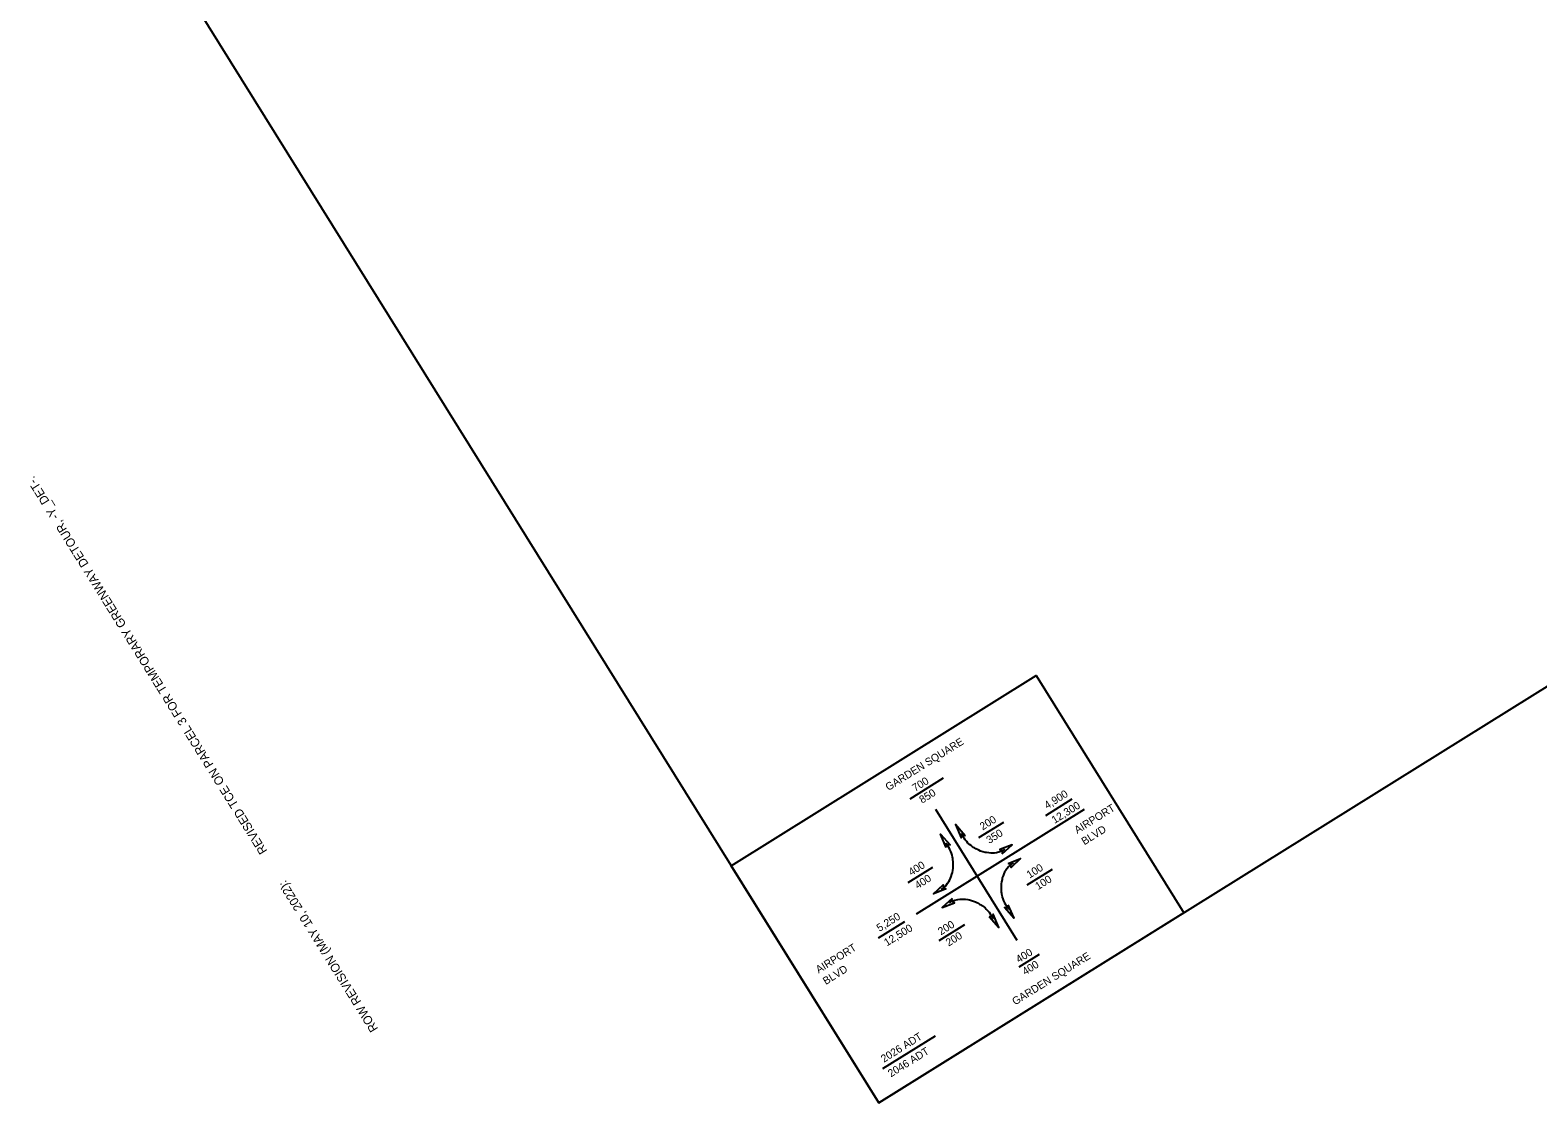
# Model space of a CAD drawing. Extents: x 2045918 to 2047994, y 757573 to 759227.
# Drawn here: x 2045918 to 2046954, y 757573 to 758310 of the extents above; entities that cross this region are included whole.
import ezdxf

# ---------------------------------------------------------------- set-up
doc = ezdxf.new("R2010")
doc.units = 0
for name, color, linetype in [('Prop Grid Mask', 7, 'Continuous'), ('Sheet Block Revision CELL', 7, 'Continuous'), ('Sheet Clip Boundary CELL', 7, 'Continuous')]:
    doc.layers.add(name, color=color, linetype=linetype)

msp = doc.modelspace()

# ---------------------------------------------------------------- linework, layer by layer
at = {"layer": 'Prop Grid Mask'}
for p, q in [((2046522.9, 757782.1), (2046545.9, 757796.4)), ((2046642.6, 757774.8), (2046527.2, 757702.9)), ((2046596.5, 757684.8), (2046540.5, 757774.8)), ((2046596.5, 757684.8), (2046540.5, 757774.8)), ((2046616.3, 757770.7), (2046634.4, 757782)), ((2046570.2, 757755.4), (2046587.3, 757766.1)), ((2046547.7, 757751.5), (2046547.5, 757751.7)), ((2046548, 757751.1), (2046547.7, 757751.5)), ((2046548.4, 757750.5), (2046548, 757751.1)), ((2046558.3, 757758.1), (2046558.2, 757758.3)), ((2046558.5, 757757.6), (2046558.3, 757758.1)), ((2046558.8, 757757), (2046558.5, 757757.6)), ((2046559.1, 757756.4), (2046558.8, 757757)), ((2046559.5, 757755.7), (2046559.1, 757756.4)), ((2046560, 757755), (2046559.5, 757755.7)), ((2046560.8, 757753.9), (2046560, 757755)), ((2046561.9, 757752.7), (2046560.8, 757753.9)), ((2046562.7, 757751.7), (2046561.9, 757752.7)), ((2046563.7, 757750.8), (2046562.7, 757751.7)), ((2046548.8, 757750), (2046548.4, 757750.5)), ((2046549.2, 757749.3), (2046548.8, 757750)), ((2046549.7, 757748.5), (2046549.2, 757749.3)), ((2046550.3, 757747.3), (2046549.7, 757748.5)), ((2046551, 757745.9), (2046550.3, 757747.3)), ((2046551.4, 757744.7), (2046551, 757745.9)), ((2046551.8, 757743.4), (2046551.4, 757744.7)), ((2046552.1, 757742), (2046551.8, 757743.4)), ((2046552.2, 757741.3), (2046552.1, 757742)), ((2046552.3, 757740.7), (2046552.2, 757741.3)), ((2046564.8, 757749.9), (2046563.7, 757750.8)), ((2046565.4, 757749.5), (2046564.8, 757749.9)), ((2046565.9, 757749.1), (2046565.4, 757749.5)), ((2046566.5, 757748.7), (2046565.9, 757749.1)), ((2046567.3, 757748.2), (2046566.5, 757748.7)), ((2046568.2, 757747.7), (2046567.3, 757748.2)), ((2046569.2, 757747.2), (2046568.2, 757747.7)), ((2046570.2, 757746.7), (2046569.2, 757747.2)), ((2046571.4, 757746.2), (2046570.2, 757746.7)), ((2046573, 757745.7), (2046571.4, 757746.2)), ((2046574.4, 757745.3), (2046573, 757745.7)), ((2046575.5, 757745.1), (2046574.4, 757745.3)), ((2046577, 757744.9), (2046575.5, 757745.1)), ((2046578.5, 757744.8), (2046577, 757744.9)), ((2046579.7, 757744.8), (2046578.5, 757744.8)), ((2046580.9, 757744.8), (2046579.7, 757744.8)), ((2046582.4, 757745), (2046580.9, 757744.8)), ((2046584.5, 757745.6), (2046582.4, 757745)), ((2046586.4, 757746.3), (2046584.5, 757745.6)), ((2046588, 757747.2), (2046586.4, 757746.3)), ((2046521.7, 757724.7), (2046538.5, 757735.2)), ((2046551.7, 757730.3), (2046552, 757731.4)), ((2046552, 757731.4), (2046552.3, 757732.8)), ((2046552.4, 757740), (2046552.3, 757740.7)), ((2046552.3, 757732.8), (2046552.5, 757734.4)), ((2046552.6, 757739), (2046552.4, 757740)), ((2046552.5, 757734.4), (2046552.6, 757735.8)), ((2046552.6, 757738), (2046552.6, 757739)), ((2046552.6, 757736.9), (2046552.6, 757738)), ((2046552.6, 757735.8), (2046552.6, 757736.9)), ((2046587.4, 757730.5), (2046586.8, 757729.2)), ((2046587.9, 757731.6), (2046587.4, 757730.5)), ((2046588.5, 757732.6), (2046587.9, 757731.6)), ((2046589.3, 757733.9), (2046588.5, 757732.6)), ((2046590.7, 757735.6), (2046589.3, 757733.9)), ((2046592.2, 757736.9), (2046590.7, 757735.6)), ((2046593.8, 757738), (2046592.2, 757736.9)), ((2046603.3, 757722.9), (2046620.7, 757733.7)), ((2046544.3, 757720), (2046545.8, 757721)), ((2046545.8, 757721), (2046547.4, 757722.4)), ((2046547.4, 757722.4), (2046548.7, 757724.1)), ((2046548.7, 757724.1), (2046549.6, 757725.3)), ((2046549.6, 757725.3), (2046550.2, 757726.4)), ((2046550.2, 757726.4), (2046550.7, 757727.5)), ((2046550.7, 757727.5), (2046551.2, 757728.8)), ((2046551.2, 757728.8), (2046551.7, 757730.3)), ((2046585.5, 757722.2), (2046585.4, 757721.1)), ((2046585.4, 757721.1), (2046585.5, 757719.9)), ((2046585.6, 757723.6), (2046585.5, 757722.2)), ((2046585.8, 757725.1), (2046585.6, 757723.6)), ((2046586.1, 757726.6), (2046585.8, 757725.1)), ((2046586.3, 757727.7), (2046586.1, 757726.6)), ((2046586.8, 757729.2), (2046586.3, 757727.7)), ((2046550, 757710.7), (2046551.7, 757711.7)), ((2046551.7, 757711.7), (2046553.6, 757712.4)), ((2046553.6, 757712.4), (2046555.7, 757712.9)), ((2046555.7, 757712.9), (2046557.2, 757713.1)), ((2046557.2, 757713.1), (2046558.4, 757713.2)), ((2046558.4, 757713.2), (2046559.6, 757713.2)), ((2046559.6, 757713.2), (2046561, 757713.1)), ((2046561, 757713.1), (2046562.6, 757712.9)), ((2046562.6, 757712.9), (2046563.7, 757712.7)), ((2046563.7, 757712.7), (2046565.1, 757712.3)), ((2046565.1, 757712.3), (2046566.6, 757711.8)), ((2046566.6, 757711.8), (2046567.9, 757711.3)), ((2046567.9, 757711.3), (2046568.9, 757710.8)), ((2046568.9, 757710.8), (2046569.9, 757710.3)), ((2046569.9, 757710.3), (2046570.7, 757709.8)), ((2046570.7, 757709.8), (2046571.6, 757709.3)), ((2046585.5, 757719.9), (2046585.5, 757719)), ((2046585.5, 757719), (2046585.6, 757718)), ((2046585.6, 757718), (2046585.7, 757717.3)), ((2046585.7, 757717.3), (2046585.8, 757716.7)), ((2046585.8, 757716.7), (2046586, 757715.9)), ((2046586, 757715.9), (2046586.3, 757714.6)), ((2046586.3, 757714.6), (2046586.7, 757713.3)), ((2046586.7, 757713.3), (2046587.1, 757712.1)), ((2046587.1, 757712.1), (2046587.7, 757710.7)), ((2046587.7, 757710.7), (2046588.4, 757709.5)), ((2046571.6, 757709.3), (2046572.2, 757708.8)), ((2046572.2, 757708.8), (2046572.7, 757708.5)), ((2046572.7, 757708.5), (2046573.3, 757708)), ((2046573.3, 757708), (2046574.4, 757707.1)), ((2046574.4, 757707.1), (2046575.3, 757706.2)), ((2046575.3, 757706.2), (2046576.2, 757705.3)), ((2046576.2, 757705.3), (2046577.2, 757704.1)), ((2046577.2, 757704.1), (2046578, 757703)), ((2046578, 757703), (2046578.5, 757702.2)), ((2046578.5, 757702.2), (2046578.9, 757701.6)), ((2046578.9, 757701.6), (2046579.3, 757701)), ((2046579.3, 757701), (2046579.6, 757700.3)), ((2046579.6, 757700.3), (2046579.8, 757699.9)), ((2046579.8, 757699.9), (2046579.9, 757699.6)), ((2046588.4, 757709.5), (2046588.8, 757708.7)), ((2046588.8, 757708.7), (2046589.3, 757708)), ((2046589.3, 757708), (2046589.6, 757707.5)), ((2046589.6, 757707.5), (2046590.1, 757706.9)), ((2046590.1, 757706.9), (2046590.4, 757706.5)), ((2046590.4, 757706.5), (2046590.6, 757706.3)), ((2046501.2, 757686.5), (2046519.2, 757697.8)), ((2046542.9, 757684.7), (2046560.6, 757695.7)), ((2046597.9, 757666.7), (2046611.8, 757675.3)), ((2046504.1, 757596.7), (2046540.4, 757619.3))]:
    msp.add_line(p, q, dxfattribs=at)
for points in [[(2046400, 757736.1), (2046609.6, 757866.7), (2046711, 757703.8), (2046501.4, 757573.3)], [(2046560.7, 757756.7), (2046554.2, 757764.4), (2046558, 757755.2), (2046558.8, 757757)], [(2046547.8, 757748.6), (2046543.8, 757757.9), (2046550.4, 757750.4), (2046548.4, 757750.5)], [(2046586.3, 757744.3), (2046593.1, 757750.5), (2046584.6, 757747.3), (2046586.4, 757746.3)], [(2046590.4, 757737.7), (2046598.9, 757741.1), (2046592.4, 757734.9), (2046592.2, 757736.9)], [(2046547.7, 757720.3), (2046539.1, 757716.9), (2046545.7, 757723.1), (2046545.8, 757721)], [(2046551.8, 757713.7), (2046545, 757707.5), (2046553.5, 757710.6), (2046551.7, 757711.7)], [(2046577.3, 757701.3), (2046583.9, 757693.6), (2046580.1, 757702.8), (2046579.3, 757701)], [(2046590.2, 757709.3), (2046594.3, 757700.1), (2046587.7, 757707.5), (2046589.7, 757707.5)]]:
    msp.add_lwpolyline(points, close=True, dxfattribs=at)
at = {"layer": 'Sheet Clip Boundary CELL'}
msp.add_lwpolyline([(2045946.3, 758464.5), (2046501.4, 757573.2), (2047629.6, 758276), (2047267.8, 758924.3), (2047213.8, 759021), (2047202.5, 759006.9), (2047161.3, 758941.5), (2047057.3, 758924.6), (2047003.6, 759005.9), (2046934.2, 758962.7), (2046881.6, 759047.1)], close=True, dxfattribs=at)

# ---------------------------------------------------------------- texts
at = {"layer": 'Prop Grid Mask'}
for s, rotation, p in [('GARDEN SQUARE', 31.918, (2046508, 757787.4)), ('700', 31.918, (2046526.4, 757786.8)), ('850', 31.918, (2046531.2, 757778.7)), ('4,900', 31.918, (2046617.1, 757774.8)), ('12,300', 31.918, (2046622.2, 757764.8)), ('AIRPORT', 31.918, (2046637.8, 757757.9)), ('200', 31.9187, (2046572.8, 757760.3)), ('BLVD', 31.918, (2046642.7, 757750.1)), ('350', 31.9187, (2046577.3, 757751)), ('400', 31.9187, (2046523.8, 757729)), ('100', 31.9187, (2046605, 757727.2)), ('400', 31.9187, (2046528.1, 757719.9)), ('100', 31.9187, (2046610.9, 757719.3)), ('5,250', 31.918, (2046501.9, 757690.6)), ('12,500', 31.918, (2046507, 757680.6)), ('200', 31.9187, (2046544.1, 757688.2)), ('200', 31.9187, (2046549.4, 757680.5)), ('AIRPORT', 31.918, (2046460.1, 757662)), ('400', 31.918, (2046597.7, 757669.1)), ('GARDEN SQUARE', 31.918, (2046595.1, 757640.1)), ('400', 31.918, (2046602, 757660.7)), ('BLVD', 31.918, (2046465, 757654.1)), ('2026 ADT', 31.918, (2046504.9, 757600.7)), ('2046 ADT', 31.918, (2046509.7, 757590.6))]:
    msp.add_text(s, height=5.25, rotation=rotation, dxfattribs=at).set_placement(p)
at = {"layer": 'Sheet Block Revision CELL'}
for s, p in [('REVISED TCE ON PARCEL 3 FOR TEMPORARY GREENWAY DETOUR, -Y_DET-.', (2046081.4, 757746.3)), ('ROW REVISION (MAY 10, 2022):', (2046157.5, 757624.1))]:
    msp.add_text(s, height=6, rotation=121.9183, dxfattribs=at).set_placement(p)

doc.saveas('drawing.dxf')
